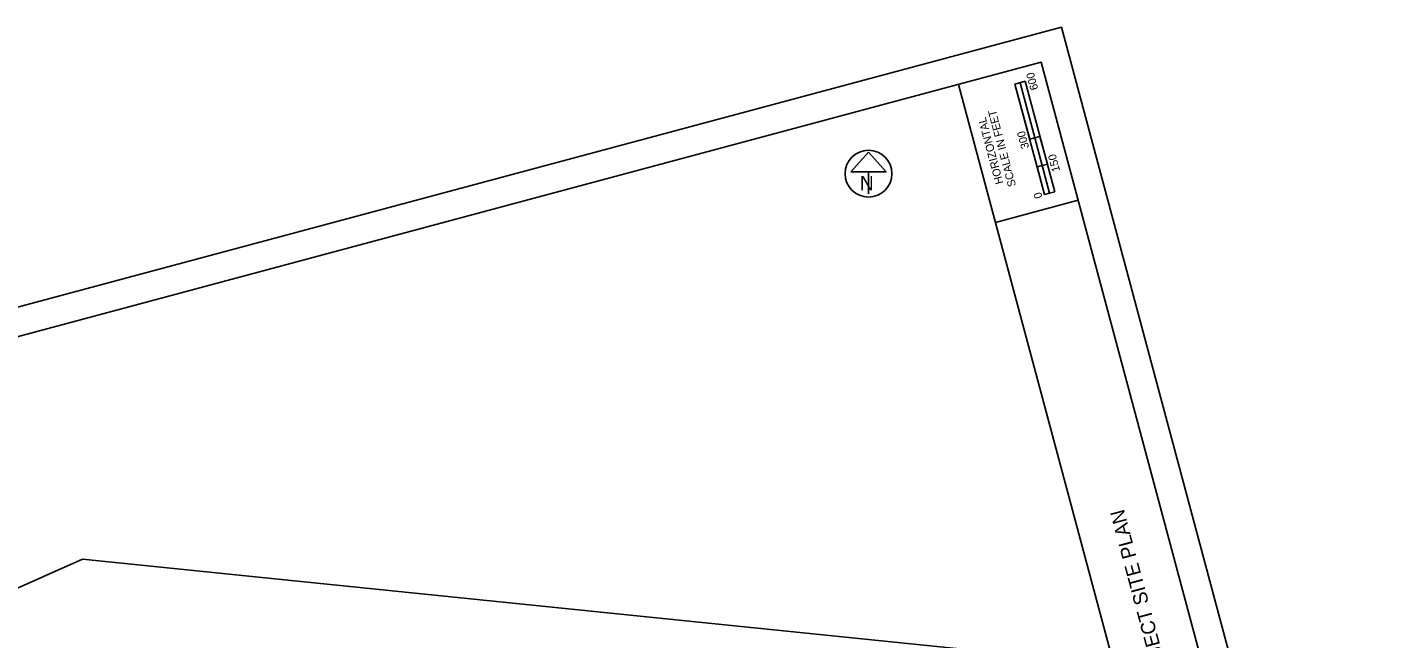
# Model space of a CAD drawing. Extents: x -361782338 to 28259792, y -263199453 to 8342113.
# Drawn here: x 1403593 to 1410730, y 579070 to 582279 of the extents above; entities that cross this region are included whole.
import ezdxf

# ---------------------------------------------------------------- set-up
doc = ezdxf.new("R2010")
doc.units = 0
for name, color, linetype in [('SC_Scratch1', 7, 'Continuous'), ('SH_Border', 7, 'Continuous'), ('SH_Cut_Line', 7, 'Continuous'), ('SH_Data', 7, 'Continuous'), ('SH_Masking', 7, 'Continuous'), ('SH_Text', 7, 'Continuous')]:
    doc.layers.add(name, color=color, linetype=linetype)

msp = doc.modelspace()

# ---------------------------------------------------------------- linework, layer by layer
at = {"layer": 'SC_Scratch1'}
msp.add_lwpolyline([(1400540.5, 577362.5), (1401030.8, 575831.8), (1401384.6, 574706.6), (1408690.6, 576642.8), (1409300.2, 577585.4), (1408847.3, 578980.3), (1403882.9, 579488), (1400534.4, 577997.6)], close=True, dxfattribs=at)
at = {"layer": 'SH_Border'}
for p, q in [((1410111.6, 575893.9), (1408481, 581979.2)), ((1408675.2, 581254.7), (1409109.8, 581371.2))]:
    msp.add_line(p, q, dxfattribs=at)
msp.add_lwpolyline([(1399642.8, 579611), (1408915.7, 582095.7), (1410546.3, 576010.3), (1401273.4, 573525.7)], close=True, dxfattribs=at)
at = {"layer": 'SH_Cut_Line'}
msp.add_lwpolyline([(1400877.5, 573264.3), (1410730, 575904.3), (1409021.8, 582279.4), (1399169.3, 579639.4)], close=True, dxfattribs=at)
at = {"layer": 'SH_Data'}
for p, q in [((1408832, 581995.6), (1408777.7, 581981)), ((1408777.7, 581981), (1408804.7, 581988.3)), ((1408933, 581401.5), (1408777.7, 581981)), ((1408855.3, 581691.2), (1408777.7, 581981)), ((1408804.7, 581988.3), (1408805, 581988.3)), ((1408805, 581988.3), (1408882.6, 581698.6)), ((1408832, 581995.6), (1408987.3, 581416)), ((1408882.6, 581698.6), (1408855.3, 581691.2)), ((1408909.4, 581705.7), (1408882.4, 581698.5)), ((1408882.4, 581698.5), (1408921.2, 581553.6)), ((1408948.2, 581560.8), (1408909.4, 581705.7)), ((1408921.2, 581553.6), (1408894.1, 581546.4)), ((1408921.2, 581553.6), (1408948.2, 581560.8)), ((1408960, 581408.7), (1408921.2, 581553.6)), ((1408894.1, 581546.4), (1408933, 581401.5)), ((1408987.3, 581416), (1408933, 581401.5)), ((1408933, 581401.5), (1408960, 581408.7))]:
    msp.add_line(p, q, dxfattribs=at)
at = {"layer": 'SH_Masking'}
msp.add_circle((1408009.4, 581510.8), 123, dxfattribs=at)
at = {"layer": 'SH_Text'}
for p, q in [((1408009.4, 581623), (1407917.1, 581520.6)), ((1408101.7, 581520.6), (1408009.4, 581623)), ((1407917.1, 581520.6), (1408101.7, 581520.6)), ((1408009.4, 581520.6), (1408009.4, 581404.6))]:
    msp.add_line(p, q, dxfattribs=at)
msp.add_circle((1408009.4, 581510.8), 123, dxfattribs=at)

# ---------------------------------------------------------------- texts
at = {"layer": 'SH_Data'}
for s, height, p in [('600', 42, (1408900.6, 581955.5)), ('SCALE IN FEET', 42, (1408784, 581448.2)), ('HORIZONTAL', 42, (1408717.5, 581461.9)), ('300', 42, (1408852.7, 581647.7)), ('150', 42, (1409015.5, 581526.8)), ('0', 42, (1408922.6, 581386.7)), ('PROJECT SITE PLAN', 75, (1409609.9, 578780.3))]:
    msp.add_text(s, height=height, rotation=105, dxfattribs=at).set_placement(p)
at = {"layer": 'SH_Text'}
msp.add_text('N', height=75, rotation=0.00002, dxfattribs=at).set_placement((1407964, 581423.4))

doc.saveas('drawing.dxf')
